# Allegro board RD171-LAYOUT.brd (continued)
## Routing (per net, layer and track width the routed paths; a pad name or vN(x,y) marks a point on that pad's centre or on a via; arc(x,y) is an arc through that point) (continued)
SIG230: length 1.6
  BOTTOM w0.4: 244.25,22.55 R149.1
SIG231: length 3.1
  BOTTOM w0.4: C72.2 233.28,17.3 ; IC14.6 234.55,17.97 234.38,17.97 233.75,18.6 233.3,18.6
SIG234: length 1.8
  BOTTOM w0.3: 234.5,16.5 233.84,16.5 233.24,15.9
  BOTTOM w0.8: IC14.5 234.5,16.5
SIG236: length 1.6
  BOTTOM w0.4: R150.1 244.25,17.8
SIG237: length 1.6
  TOP w0.4: C73.2 233.78,19.57 234.03,19.83 234.55,19.83 IC15.6
SIG242: length 1.8
  TOP w0.3: 233.24,22.1 233.79,21.55 233.95,21.55 234.5,21.3
  TOP w0.8: IC15.5 234.5,21.3
SIG245: length 1.9
  TOP w0.3: 234.5,16.5 234.05,16.7 234.04,16.7 233.24,17.5
  TOP w0.8: IC16.5 234.5,16.5
SIG246: length 2.7
  TOP w0.4: IC16.6 234.28,15.23 234,14.95 233.35,14.95 ; C74.2 233.32,16.1
SIG247: length 1.6
  TOP w0.4: IC15.1 245.8,20.03
SIG249: length 41.5
  TOP w0.3: 172.88,117.3 174.15,117.3 175.15,116.3 v1(176.9,116.3)
  TOP w0.45: 155.18,107.1 155.75,107.1 156.3,107.65 156.3,107.92
  TOP w0.55: 154.55,107.1 IC5.11 155.18,107.1
  TOP w0.6: 154.95,118.75 155.95,117.75 D23.A 156.9,116.6 158.25,115.25 158.25,109 157.1,107.85 156.4,107.85 ; 154.95,118.75 154.4,118.75 ; 154.95,118.75 154.4,119.3 ; 154.4,120.9 153.8,121.5 ; 154.4,120.9 155,121.5 ; 154.4,120.9 Q5.S ; 154.4,120.9 154.4,119.3 ; 154.4,119.3 154.4,118.75 ; 154.4,119.3 153.85,118.75 ; 154.4,118.75 153.85,118.75 ; 153.85,118.75 R28.1
  TOP w1.7: 172.88,117.3 TP15.1
  CONDUCTIVE3 w0.6: v1(176.9,116.3) 174.25,116.3
SIGN254: length 1.5
  TOP w0.7: 152.25,44.7 152.25,44 152.15,43.9 R172.1
SIGN256: length 6.5
  TOP w0.3: v1(145.65,2.3) 144.57,2.3
  TOP w0.7: 144.57,2.3 R177.1
  BOTTOM w0.3: 146.55,3.85 146.55,4.55
  BOTTOM w0.4: 146.55,3.85 C77.2 R96.2 146.35,2 145.95,2 v1(145.65,2.3) 145.3,1.95 144.7,1.95 R97.1
SIGN260: length 7
  BOTTOM w0.3: 146.57,5.22 147.43,5.22 148.45,4.2 149.08,4.2 150.57,2.7 150.57,2.36 ; 151.66,1.7 151.07,1.7 C76.2
  BOTTOM w0.45: 150.57,2.36 C76.2
  BOTTOM w0.58: 151.66,1.7 R170.2 151.86,1.7
SIGN262: length 6.7
  BOTTOM w0.3: 151.66,3.1 151.05,3.1 150.07,4.08 C75.2 149.68,4.9 148.65,4.9 147.68,5.88 146.55,5.88
  BOTTOM w0.58: 151.86,3.1 R169.2 151.66,3.1
SIGN266: length 20.2
  TOP w0.3: 159.35,49.95 160.25,49.95 160.85,49.35 160.85,45.7 156.65,41.5
  TOP w1: 158.95,49.95 158.85,50.05 158.85,51.03 Q2.G
  TOP w1.3: 158.95,49.95 159.35,49.95
SIGN267: length 18.4
  TOP w0.3: 122.5,59.05 122.9,58.65 ; 122.5,59.05 122.5,56.2 ; 122.5,59.05 122.1,58.65 ; 122.5,59.05 122.5,62.4 124,63.9 TP4.1
  TOP w1: 122.75,53.9 122.25,53.4 ; 122.25,53.4 121.75,53.9 ; 122.25,53.4 122.25,55.95 122.5,56.2 ; 122.25,53.4 122.25,52.51 121.5,51.76 FB2.2
SIGN269: length 12.5
  TOP w0.6: IC5.12 153.58,108.37 153.25,108.7 153.25,112.65 152.4,113.5 D42.A 152.4,114.6 ; 152.4,114.6 D43.C ; 152.4,114.6 D23.C
SIGN270: length 1.7
  TOP w0.6: R114.1 149.22,100.55
SIGN271: length 2.3
  BOTTOM w1.5: 168.15,18.3 R179.2 168.15,20.6
SIGN275: length 3
  TOP w0.3: 87.3,78.43 87.3,78.75 86.91,79.14 85.3,79.14
  TOP w0.4: 87.3,78.05 D48.A 87.3,78.43
  TOP w0.7: 85.2,79.14 85.3,79.14
SIGN284: length 1.6
  BOTTOM w0.4: IC13.3 245.8,20.03
SIGN287: length 1.6
  BOTTOM w0.4: IC14.3 245.8,15.23
SIGN289: length 1.6
  TOP w0.4: R197.1 244.25,17.8
SIGN291: length 1.6
  TOP w0.4: R196.1 244.25,22.6
SIGN304: length 2.9
  BOTTOM w0.4: IC21.2 229.68,20.8 229.88,20.6 R186.1 231.6,20.6 R153.1
SIGN305: length 3.1
  BOTTOM w0.4: IC22.2 229.65,16.5 230.05,16.1 230.5,16.1 R188.1 230.5,15.9 R154.1
SIGN314: length 3.8
  TOP w0.4: R155.1 230.85,22 230.5,21.65 R190.1 230.25,21 229.85,20.6 IC23.2
SIGN315: length 3.2
  TOP w0.4: IC24.2 229.6,16.4 230.4,17.2 R192.1 ; R156.1 231.6,17.3 230.55,17.3
SIGN318: length 16.2
  TOP w0.6: D24.C 153.9,69.5 154.9,69.5 157.2,71.8 160.25,71.8 D41.C 163.05,73.05 D40.A ; IC4.12 164.83,71.27 163.65,72.45
SIGN322: length 35.7
  TOP w0.6: IC5.6 150.94,104.56 153.1,102.4 v1(156.2,102.4)
  BOTTOM w0.6: v1(156.2,102.4) 156.2,103.95 165.7,113.45 171.75,113.45 172.65,114.35 D22.C 170.1,115.1 ; 170.1,115.1 D47.C ; 170.1,115.1 D46.A
SIGN325: length 12.1
  TOP w0.6: 171.5,72.7 D44.A 170.85,69.85 170.85,68.8 168.64,66.59 IC4.6 ; D25.C 169.35,72.75 D45.C
SIGN336: length 1.6
  BOTTOM w0.6: 260.1,93 R20.1
SIGN337: length 1.6
  BOTTOM w0.6: D54.A R213.1
SIGN338: length 2.2
  BOTTOM w0.6: R18.1 254.05,109.55
SIGN339: length 3
  BOTTOM w0.6: D52.A 254.85,112.8 ; 254.85,112.8 255.6,112.8 ; 254.85,112.8 255.45,113.4
SIGN341: length 1.7
  BOTTOM w0.6: 262.1,50.3 R24.1 D57.C
SIGN342: length 1.6
  BOTTOM w0.6: D58.A 262,52.45
SIGN343: length 21.3
  TOP w0.6: v1(257.75,76.45) 256.45,76.45 ; 256.75,87.05 Q7.4 v1(256.75,88.05)
  CONDUCTIVE4 w0.6: v1(257.75,76.45) 258,76.7 258,80.05 256.75,81.3 v1(256.75,82.25) v1(256.75,88.05)
  BOTTOM w0.5: R22.2 258.8,71.9 R23.2
  BOTTOM w0.6: v1(256.75,82.25) Q8.4 ; v1(257.75,76.45) 258.8,75.4 R214.2 R23.2
SIGN344: length 2.2
  BOTTOM w0.6: R23.1 254.05,71.55
SIGN345: length 2.8
  BOTTOM w0.6: 254.85,74.8 255.45,75.4 ; 254.85,74.8 D56.A ; 254.85,74.8 255.4,74.8
SIGN355: length 191
  TOP w3.5: T4.1 224.19,41 221.48,43.71 220.28,44.72 218.92,45.51 217.45,46.04 215.9,46.32 215.12,46.35 203.59,46.35 202.98,46.38 201.78,46.59 200.63,47.01 199.57,47.62 198.64,48.4 192.46,54.58 192.1,54.97 191.5,55.83 191.06,56.77 190.79,57.78 190.7,58.83 190.7,64.64 190.64,65.34 190.46,66.01 190.16,66.64 189.76,67.21 189.53,67.47 189.5,67.5 189.5,71.7
  BOTTOM w1: 155.05,92.8 155.8,92.05 ; 155.8,92.05 155.1,91.35 ; 155.8,92.05 170.1,92.05 173.05,95 182.45,95 D19.C
  BOTTOM w3: 148.95,123.8 148.95,117.25 149.47,116.73 149.47,99.58 153.95,95.1 153.95,81.5
  BOTTOM w3.5: 184.95,72.05 189.53,67.47 189.76,67.21 190.16,66.64 190.46,66.01 190.64,65.34 190.7,64.64 190.7,58.83 190.79,57.78 191.06,56.77 191.5,55.83 192.1,54.97 192.46,54.58 198.64,48.4 199.57,47.62 200.63,47.01 201.78,46.59 202.98,46.38 203.59,46.35 215.12,46.35 215.91,46.32 217.45,46.04 218.93,45.51 220.28,44.72 221.49,43.71 224.2,41 T4.1
  vias: v1(188.2,73.6) v1(188.2,72.6) v1(188.2,71.6) v1(188.2,70.6) v1(188.2,69.6) v1(189.2,74.6) v1(189.2,73.6) v1(189.2,72.6) v1(189.2,71.6) v1(189.2,70.6) v1(189.2,69.6) v1(189.2,68.6) v1(190.2,74.6) v1(190.2,73.6) v1(190.2,72.6) v1(190.2,71.6) v1(190.2,70.6) v1(190.2,69.6) v1(190.2,68.6) v1(191.2,73.6) v1(191.2,72.6) v1(191.2,71.6) v1(191.2,70.6) v1(191.2,69.6) v1(191.2,68.6)
SIGN356: length 3.8
  BOTTOM w0.6: T4.5 D14.A R9.2
SIGN360: length 4.8
  BOTTOM w2.8: 262.25,38.2 L5.1 262.25,33.4
SIGN364: length 72.3
  TOP w5: 92.28,50.4 89.98,50.4 88.41,48.83 83.42,48.83 78.54,53.7 76.1,53.7 ; 104.9,32.2 102.75,32.2 C64.2 93.35,43.55
  BOTTOM w5: 104.75,32.2 102.75,32.2 C64.2 93.35,43.55 ; 76.1,53.7 78.54,53.7 83.42,48.83 88.41,48.83 89.98,50.4 92.28,50.4
SIGN366: length 5.3
  TOP w0.5: 129.6,66.13 129.6,68.25 HS1.1
  TOP w0.72: 129.6,65.84 R220.2 129.6,66.13
SIGN369: length 5.3
  TOP w0.5: HS2.1 183,66.52
  TOP w0.7: 183,66.52 R221.2
SIGN371: length 5.3
  TOP w0.5: HS3.1 116.3,47.15 116.3,45.02
  TOP w0.6: 116.3,44.75 R222.2 116.3,45.02
SIGN373: length 5.8
  TOP w0.5: HS4.1 184.6,84.5 184.6,82.02
  TOP w0.6: 184.6,82.02 184.6,81.75
VREF: length 63.1
  TOP w0.6: v1(265.7,23.35) v1(266.95,23.35) 266.95,19.46 266.4,18.91 R207.2 ; R58.2 267.7,13.85 R62.2 v1(268.3,15.35) v1(268.3,16.65) 268.3,16.85 267.7,17.45 266.45,17.45
  CONDUCTIVE3 w0.8: v1(268.3,16.65) v1(268.3,15.35)
  CONDUCTIVE3 w1: 253,13.15 253,13.75 ; 253,13.15 253,12.2 252,11.2 v1(251.4,11.2) ; 253,13.15 252.4,13.75 ; 253,13.75 253,14.35 ; 253,13.75 252.4,13.75 ; 253,14.35 253,18.65 256.05,21.7 262.45,21.7 264.1,23.35 v1(265.7,23.35) ; 253,14.35 252.4,13.75 ; v1(268.3,16.65) 268.3,18.55 266.95,19.9 266.95,22.1 ; 266.95,22.1 v1(266.95,23.35) v1(265.7,23.35) ; 266.95,22.1 v1(265.7,23.35) ; 252.4,13.75 v1(251.4,13.75)
  BOTTOM w0.4: v1(251.4,13.75) R211.2
  BOTTOM w0.45: 262.95,23.15 C99.2
  BOTTOM w0.6: v1(266.95,23.35) v1(265.7,23.35) R44.2 263.15,23.35 262.95,23.15 ; R57.2 267,16.65 v1(268.3,16.65) v1(268.3,15.35) R62.2 268.3,14.4 ; v1(251.4,11.2) 251.65,10.95 252.25,10.95
VREF_PFC: length 40.9
  TOP w0.3: R177.2 145.2,3.7 v1(145.65,3.6)
  CONDUCTIVE3 w0.5: v1(136.3,4.75) v1(137.55,4.75) 144.5,4.75 v1(145.65,3.6) 147,4.95 147,14.75 144.5,17.25 v1(143.65,17.25)
  BOTTOM w0.3: IC3.13 139.6,5.88 139.12,5.4 C42.2 ; 150.05,14.84 147.64,17.25 v1(143.65,17.25)
  BOTTOM w0.4: R97.2 144.95,3.6 v1(145.65,3.6)
  BOTTOM w0.45: C42.2 138.35,5.17 137.93,4.75 v1(137.55,4.75)
  BOTTOM w0.6: v1(136.3,4.75) v1(137.55,4.75)
N03591: length 1.3
  BOTTOM w0.7: R130.1 R116.2
N05004: length 11.7
  TOP w0.6: 144.1,121.5 143.52,120.92 ; 143.52,120.92 Q5.G ; 143.52,120.92 142.94,121.5 ; 143.52,120.92 143.52,119.4 144.17,118.75 R28.2 R133.2 R132.2
N07003: length 4.8
  BOTTOM w2.8: 267.98,83.75 L6.1 267.98,88.55
N07203: length 21.1
  TOP w0.6: v1(257.75,114.45) 256.6,114.45 ; v1(258.07,125.18) 256.9,125.18
  CONDUCTIVE4 w0.6: v1(258.07,125.18) 257.7,125.18 257,124.48 v1(257,120.25) 257,118.8 258,117.8 258,114.7 v1(257.75,114.45)
  BOTTOM w0.5: R18.2 258.8,109.9 R19.2
  BOTTOM w0.6: R18.2 R212.2 258.8,113.4 v1(257.75,114.45) ; v1(257,120.25) 257,121.3
N11927: length 63
  TOP w0.6: v1(288.75,23.95) TP28.1
  TOP w0.8: v1(301.1,58.95) 301.1,57.65 ; v1(307.6,58.95) 307.6,57.65
  CONDUCTIVE4 w0.3: v1(291.2,36.95) 291.7,36.7 293.65,34.75 293.65,28.85 v1(288.75,23.95)
  CONDUCTIVE4 w0.8: v1(291.2,36.95) 289.8,38.35 289.8,55.6 293.15,58.95 v1(301.1,58.95) v1(307.6,58.95)
  BOTTOM w0.8: 291.2,36.05 v1(291.2,36.95) ; Q18.4 307.4,58.76 v1(307.6,58.95) ; Q17.4 300.9,58.76 v1(301.1,58.95)
N043041: length 1.9
  TOP w0.6: 161.65,75.3 D40.C
N043160: length 2.6
  TOP w0.6: D41.A R127.1
N043261: length 1.6
  TOP w0.6: D44.C R134.1
N043380: length 1.6
  TOP w0.6: D45.A R135.1
N043600: length 1.6
  TOP w0.6: R133.1 149.6,116.9
N043701: length 1.6
  BOTTOM w0.6: R136.1 D46.C
N043820: length 1.6
  BOTTOM w0.6: R137.1 D47.A
N66342: length 37.6
  TOP w0.5: 181.31,21.81 184.38,21.81 186.92,24.35 Q80.D
  TOP w1: T8.3 209.97,24.5
  TOP w1.68: 180.1,21.81 181.31,21.81
  TOP w1.9: 189.55,23.45 Q80.D
  TOP w2: 189.55,23.45 190.94,23.45 195.69,18.7 207.15,18.7 209.97,21.52 209.97,24.5
N66362: length 4.5
  BOTTOM w0.6: 188.6,33.45 191.95,33.45 ; 188.6,33.45 188.6,34.55 ; 188.6,33.45 R803.1
N14550647: length 5.4
  BOTTOM w0.4: 184.47,46.75 R809.2 R808.1 ; 184.47,46.75 184.6,46.75 ; 184.47,46.75 C812.2 ; 184.47,45.6 IC80.VS
N14553110: length 30.8
  BOTTOM w2: 242.45,5.45 239,2 213.1,2
N14557584: length 84.3
  CONDUCTIVE4 w0.3: C800.2 191.15,17.6 189.11,19.64 185.41,19.64 178.85,26.2 v1(178.85,30.4)
  BOTTOM w0.3: v1(178.85,30.4) 181.05,32.6 181.05,35.7 182.5,37.15 183,37.15
  BOTTOM w0.59: 183,37.15 183.2,37.15
  BOTTOM w1: F8.2 180.45,15
  BOTTOM w2: 217.4,24.5 217.4,22.1 211.95,16.65 191.4,16.65 ; 191.4,16.65 191.4,16.65 ; 191.4,16.65 191.4,16.66 ; T8.1 217.39,30.59 R800.2 ; 180.45,15.25 180.45,15.37 180.46,15.55 180.52,15.89 180.64,16.22 180.81,16.52 181.04,16.79 183.56,19.31 183.69,19.43 183.98,19.63 184.29,19.78 184.63,19.87 184.98,19.9 187.32,19.9 187.5,19.89 187.84,19.83 188.17,19.71 188.47,19.54 188.74,19.31 191.4,16.66 ; 191.4,16.65 191.4,16.66 ; 191.4,16.65 191.4,15.59
N14557651: length 1.4
  BOTTOM w0.6: D81.C 178.55,45.15 178.2,44.8
N14557692: length 3.5
  BOTTOM w0.6: 183.2,42.6 IC80.VDD C802.2 R806.2
N14557973: length 1.9
  BOTTOM w0.4: 185.74,44.45 185.74,42.6
N14565222: length 2.2
  BOTTOM w0.6: 185.74,37.2 185.74,36.06 R802.1
N14565783: length 2.7
  BOTTOM w0.6: IC80.CS C803.2 ; R804.1 188.6,37.15
N14565980: length 6.2
  TOP w1.5: T8.5 200.92,29.97 v1(201.45,30.5)
  vias: v1(201.45,31.4) v1(202.35,31.4) v1(202.35,30.5)
N16776505: length 4.8
  BOTTOM w0.6: 186.11,29.35 186.5,30.5 186.5,31.95 ; R803.2 186.5,32
N16975142: length 20.3
  TOP w6.1: T6.4 T6.3
  BOTTOM w6.1: T6.4 T6.3
N16985418: length 20.3
  TOP w6.1: T5.4 T5.3
  BOTTOM w6.1: T5.4 T5.3

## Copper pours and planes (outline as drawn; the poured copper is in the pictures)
P48V on TOP: 294.5,55.73 294.5,55.75 294.51,55.76 294.96,56.21 294.98,56.22 295,56.23 315.45,56.23 315.47,56.22 315.49,56.21 315.74,55.96 315.75,55.95 315.75,55.93 315.75,36.21 315.75,36.19 315.74,36.17 312.83,33.26 312.81,33.25 312.79,33.25 297.47,33.25 297.45,33.25 297.44,33.26 294.51,36.19 294.5,36.2 294.5,36.22 ; 4 cut-outs
P48V on BOTTOM: 294.5,55.73 294.5,55.75 294.51,55.76 294.96,56.21 294.98,56.22 295,56.23 313.45,56.23 313.47,56.22 313.49,56.21 313.86,55.84 313.89,55.8 313.9,55.74 313.9,32.95 313.89,32.92 313.66,31.96 314.14,31.11 314.15,31.1 315.09,30.16 315.1,30.15 315.1,30.13 315.1,28.95 315.09,28.91 315.05,28.9 314.04,28.9 314.01,28.91 313.46,29.46 313.25,29.6 313,29.65 308.09,29.65 307.9,29.61 307.73,29.5 306.86,28.63 306.83,28.61 306.79,28.6 304.9,28.6 304.87,28.61 304.78,28.72 304.75,28.85 304.75,29.83 304.73,29.94 304.66,30.04 303.19,31.51 303.08,31.62 302.94,31.72 302.76,31.75 295.02,31.75 295,31.75 294.99,31.76 294.51,32.24 294.5,32.25 294.5,32.27 ; 4 cut-outs
P48V on CONDUCTIVE2, CONDUCTIVE5: 301.42,46.1 301.4,46.1 301.39,46.11 300.66,46.84 300.65,46.85 300.65,46.87 300.65,50.73 300.65,50.75 300.66,50.76 300.79,50.89 300.8,50.9 300.82,50.9 309.48,50.9 309.5,50.9 309.51,50.89 310.24,50.16 310.25,50.15 310.25,50.13 310.25,46.27 310.25,46.25 310.24,46.24 310.11,46.11 310.1,46.1 310.08,46.1
P48V on CONDUCTIVE3: 294.5,55.73 294.5,55.75 294.51,55.76 294.96,56.21 294.98,56.22 295,56.23 315.5,56.23 315.52,56.22 315.54,56.21 315.78,55.97 315.8,55.95 315.8,55.93 315.8,36.19 315.8,36.17 315.79,36.15 312.9,33.26 312.88,33.25 312.86,33.25 297.47,33.25 297.45,33.25 297.44,33.26 294.51,36.19 294.5,36.2 294.5,36.22 ; 1 cut-out
VCC12R0_1 on TOP: 176.52,40.15 176.5,40.15 176.49,40.16 176.01,40.64 176,40.65 176,40.67 176,41.83 176,41.85 176.01,41.86 176.24,42.09 176.25,42.1 176.27,42.1 177.33,42.1 177.35,42.1 177.36,42.09 177.59,41.86 177.6,41.85 177.6,41.83 177.6,40.75 177.6,40.73 177.59,40.71 177.04,40.16 177.02,40.15 177,40.15
VCC12R0_2 on BOTTOM: 247.05,1.6 247.01,1.61 247,1.65 247,3.27 246.97,3.37 246.94,3.41 246.61,3.74 246.6,3.75 246.6,3.77 246.6,9.58 246.6,9.6 246.61,9.61 248.14,11.14 248.19,11.23 248.2,11.28 248.2,12.9 248.21,12.94 248.25,12.95 249.55,12.95 249.59,12.94 249.6,12.9 249.6,9.98 249.63,9.88 249.66,9.84 250.2,9.3 250.29,9.25 250.34,9.24 267.95,9.24 267.97,9.24 267.99,9.23 268.58,8.64 268.59,8.62 268.6,8.6 268.6,7.95 268.59,7.93 268.58,7.92 268.13,7.46 268.13,6.05 268.12,6.01 268.08,6 249.08,6 248.98,5.97 248.94,5.94 248.06,5.06 248.01,4.97 248,4.92 248,1.65 247.99,1.61 247.95,1.6
AUX on BOTTOM: 196.45,24.45 196.41,24.46 196.4,24.5 196.4,26.25 196.65,26.5 197.95,26.5 197.99,26.49 198,26.45 198,25.27 198,25.25 197.99,25.24 197.96,25.21 197.91,25.12 197.9,25.07 197.9,24.5 197.89,24.46 197.85,24.45
CONN002 on TOP: 146.91,78.8 146.91,84.2 150.09,84.2 150.09,78.8
CONN002 on BOTTOM: 169.91,78.9 169.81,78.94 169.76,79.05 169.76,84.05 169.81,84.16 169.91,84.2 172.79,84.2 172.89,84.16 172.94,84.05 172.94,79.05 172.89,78.94 172.79,78.9
CONN002 on BOTTOM: 148.99,78.8 148.96,78.81 148.93,78.82 146.93,80.82 146.92,80.84 146.91,80.87 146.91,84.12 146.93,84.18 146.99,84.2 150.01,84.2 150.07,84.18 150.09,84.12 150.09,78.88 150.07,78.82 150.01,78.8
CONN002 on CONDUCTIVE3: outline of 127 points within 146.65,79 205.5,125.79
CONN002 on CONDUCTIVE4: outline of 133 points within 146.65,79 205.5,125.79 ; 1 cut-out
CONN003 on TOP: 201.65,51.49 201.63,51.49 201.62,51.5 195.5,57.63 195.13,58.18 195,58.83 195,64.64 194.8,66.44 194.22,68.15 194.15,68.31 194.15,68.33 194.15,73.68 193.95,74.69 193.37,75.55 192.15,76.77 192.09,76.83 191.26,77.36 190.28,77.55 189.42,77.55 189.4,77.55 189.39,77.56 189.16,77.79 189.15,77.8 189.15,77.82 189.15,81.58 189.15,81.6 189.16,81.61 189.39,81.84 189.4,81.85 189.42,81.85 195.88,81.85 195.91,81.84 198.09,79.66 198.1,79.65 198.1,79.63 198.1,63.79 198.53,61.65 199.74,59.83 202.86,56.71 203.71,56.71 203.73,56.71 203.74,56.7 206.05,54.39 206.05,54.37 206.05,52.62 206.05,52.6 206.04,52.59 204.95,51.5 204.94,51.49 204.92,51.49
CONN003 on BOTTOM: outline of 111 points within 174.2,51.49 206.05,117.05
CONN004 on TOP: outline of 140 points within 274.4,48 313.45,123.05
CONN004 on BOTTOM: outline of 134 points within 275.9,48 309.5,123.05
CONN004 on CONDUCTIVE2, CONDUCTIVE5: 296.12,59.9 296.1,59.9 296.09,59.91 295.36,60.64 295.35,60.65 295.35,60.67 295.35,66.93 295.35,66.95 295.36,66.96 295.49,67.09 295.5,67.1 295.52,67.1 301.78,67.1 301.8,67.1 301.81,67.09 302.54,66.36 302.55,66.35 302.55,66.33 302.55,60.07 302.55,60.05 302.54,60.04 302.41,59.91 302.4,59.9 302.38,59.9
CONN004 on CONDUCTIVE3: 281.45,102.33 281.43,102.44 281.36,102.54 274.41,109.49 274.4,109.5 274.4,109.52 274.4,122.78 274.41,122.81 274.69,123.09 274.7,123.1 274.72,123.1 282.08,123.1 282.1,123.1 282.11,123.09 287.71,117.49 288.03,117.28 288.41,117.2 296.03,117.2 296.05,117.2 296.06,117.19 296.96,116.29 297.27,116.08 297.66,116 306.21,116 306.28,115.97 309.47,112.78 309.5,112.71 309.5,66.66 309.57,66.41 309.65,66.3 313.44,62.51 313.45,62.5 313.45,62.48 313.45,57.12 313.39,56.98 313.25,56.92 295,56.92 294.98,56.93 294.96,56.94 294.52,57.38 294.5,57.4 294.5,57.42 294.5,83.35 294.47,83.42 294.4,83.45 293.9,83.45 293.83,83.42 293.8,83.35 293.8,48.97 293.8,48.95 293.79,48.94 292.86,48.01 292.85,48 292.83,48 283.32,48 283.3,48 283.29,48.01 281.46,49.84 281.45,49.85 281.45,49.87 ; 2 cut-outs
FG2 on TOP: 4.5,7.35 4.54,7.46 4.65,7.5 9.58,7.5 9.65,7.49 9.79,7.41 12.91,4.29 12.96,4.23 13,4.08 13,3.56 12.99,3.5 12.96,3.46 10.09,0.59 10.03,0.54 9.88,0.5 6,0.5 5.41,0.62 4.94,0.94 4.61,1.44 4.5,2 ; 1 cut-out
FG3 on TOP: 61.35,42.52 61.33,42.53 61.31,42.54 60.54,43.31 60.53,43.33 60.52,43.35 60.52,49.93 60.57,50.03 60.67,50.08 61.83,50.08 61.93,50.03 61.98,49.92 61.98,49.47 61.98,49.43 62,49.4 65.11,46.29 65.14,46.25 65.15,46.19 65.17,46.17 65.17,46.15 65.17,45.73 67.13,43.77 67.17,43.66 67.17,42.67 67.13,42.57 67.03,42.52
FG3 on BOTTOM: 60.67,44.35 60.57,44.39 60.52,44.5 60.52,49.92 60.57,50.03 60.67,50.08 61.83,50.08 61.93,50.03 61.98,49.92 61.98,49.47 61.98,49.43 62,49.4 64.71,46.69 64.74,46.65 64.75,46.59 64.75,44.5 64.71,44.39 64.6,44.35
FG3 on BOTTOM: 63.9,42.52 63.79,42.57 63.75,42.67 63.75,43.85 63.79,43.96 63.9,44 64.9,44 64.9,44.55 64.94,44.66 65.05,44.7 66.14,44.7 66.2,44.69 66.24,44.66 67.01,43.89 67.05,43.79 67.05,42.67 67.01,42.57 66.9,42.52
FG5 on BOTTOM: 176.54,1.61 176.47,1.71 176.45,1.82 176.45,2.58 176.47,2.69 176.54,2.79 177.66,3.91 177.76,3.98 177.87,4 178.6,4 178.71,3.96 178.75,3.86 181.25,1.5 183.75,3.86 183.75,3.88 183.75,5.78 183.78,5.83 183.84,5.81 187.55,2.1 188.35,2.1 188.39,2.09 188.4,2.05 188.4,1.35 188.39,1.31 188.35,1.3 187.55,1.3 186.76,0.51 186.75,0.5 186.73,0.5 177.77,0.5 177.66,0.52 177.56,0.59
FG6 on BOTTOM: 307.58,4.8 307.6,4.8 307.61,4.79 308.11,4.29 308.21,4.22 308.32,4.2 311.1,4.2 311.4,4.5 311.4,10.56 316.37,15.54 316.53,15.81 316.55,15.96 316.55,28.03 316.52,28.2 316.42,28.35 316.31,28.45 316.3,28.49 316.3,30.15 316.31,30.19 316.35,30.2 317.38,30.2 317.4,30.19 317.51,30.14 317.99,29.66 318,29.63 318,2 317.56,0.94 316.5,0.5 307.87,0.5 307.76,0.52 307.66,0.59 307.09,1.16 307.02,1.26 307,1.37 307,4.75 307.01,4.79 307.05,4.8 ; 2 cut-outs
FG7 on BOTTOM: 308.2,121.5 308.24,121.61 308.35,121.65 309.15,121.65 309.38,121.88 309.42,121.91 309.48,121.92 310.52,121.92 310.63,121.94 310.73,122.01 310.87,122.15 310.95,122.29 310.96,122.36 310.96,124.72 311,124.83 312.59,126.41 312.65,126.46 312.8,126.5 316.5,126.5 317.09,126.38 317.56,126.06 317.89,125.56 318,125 318,123.05 318,123.04 315.6,119.68 311.66,120.95 308.35,120.95 308.24,120.99 308.2,121.1 ; 1 cut-out
HS1_1 on TOP (solid shape): 181.37,125.3 181.31,125.72 181.73,125.77 185.03,123.24 185.15,123 185.03,122.76 181.73,120.23 181.42,120.19 181.25,120.46 181.28,120.6 181.37,120.7 182.08,121.25 182.08,124.75
HS1_2 on TOP (solid shape): 88.33,125.75 88.6,125.78 88.74,125.55 88.71,125.44 88.64,125.36 87.93,124.79 87.93,121.21 88.64,120.64 88.68,120.29 88.33,120.25 85.1,122.8 85,123 85.1,123.2
IN on TOP (solid shape): 196.3,36.86 196.35,36.85 197.27,36.63 197.55,36.45 197.66,36.14 197.6,35.9 197.43,35.72 197.13,35.26 196.59,35.35 195.78,36.16 195.74,36.36 195.88,36.72 196.24,36.86
LGND on TOP: outline of 236 points within 254.53,6.85 318,126.5 ; 5 cut-outs
LGND on TOP: outline of 85 points within 254.53,63.5 265.06,88.25
LGND on BOTTOM: 260.4,69.6 260.1,69.9 260.1,76.7 259.9,76.9 259.47,76.9 259.45,76.9 259.44,76.91 259.26,77.09 259.25,77.1 259.25,77.12 259.25,78.53 259.25,78.55 259.26,78.56 259.54,78.84 259.55,78.85 259.57,78.85 262.05,78.85 262.09,78.84 262.1,78.8 262.1,69.6
LGND on BOTTOM: outline of 103 points within 256.02,33.5 317,126.5 ; 7 cut-outs
LGND on BOTTOM: 303.55,28.6 303.68,28.28 304,28.15 306.79,28.15 307,28.19 307.18,28.31 308.05,29.19 308.07,29.2 308.09,29.2 313,29.2 313.08,29.18 313.14,29.14 313.7,28.58 313.9,28.47 314.02,28.45 315.63,28.45 315.65,28.45 315.66,28.44 316.09,28.01 316.1,28 316.1,27.98 316.1,15.96 316.06,15.86 310.99,10.79 310.92,10.69 310.9,10.58 310.9,5.94 310.89,5.88 310.86,5.83 310.78,5.75 310.65,5.56 310.6,5.33 310.6,5 310.56,4.89 310.45,4.85 308.27,4.85 308.25,4.85 308.24,4.86 307.89,5.21 307.79,5.28 307.68,5.3 298.72,5.3 298.61,5.32 298.51,5.39 297.34,6.56 297.02,6.77 296.64,6.85 295.07,6.85 294.96,6.87 294.86,6.94 294.54,7.26 294.51,7.3 294.5,7.36 294.5,30.78 294.5,30.8 294.51,30.81 294.99,31.29 295,31.3 295.02,31.3 302.73,31.3 302.75,31.3 302.76,31.29 303.54,30.51 303.55,30.5 303.55,30.48 ; 3 cut-outs
LGND on BOTTOM: 243.12,1.6 243.1,1.6 243.09,1.61 242.91,1.79 242.9,1.8 242.9,1.82 242.9,2.98 242.9,3 242.91,3.01 243.09,3.19 243.1,3.2 243.12,3.2 244.75,3.2 244.79,3.19 244.8,3.15 244.8,1.65 244.79,1.61 244.75,1.6
LGND on BOTTOM: 256.67,63.5 256.65,63.5 256.64,63.51 256.29,63.86 256.28,63.88 256.27,63.9 256.27,65.24 256.19,65.45 255.97,65.54 254.68,65.54 254.57,65.58 254.53,65.69 254.53,68.88 254.54,68.92 254.57,68.93 255.85,68.93 255.95,68.96 255.99,68.99 256.24,69.24 256.29,69.33 256.3,69.38 256.3,70.08 256.3,70.1 256.31,70.11 256.59,70.39 256.6,70.4 256.62,70.4 259.38,70.4 259.4,70.4 259.41,70.39 259.64,70.16 259.65,70.15 259.65,70.13 259.65,69.73 259.68,69.63 259.71,69.59 260.14,69.16 260.23,69.11 260.28,69.1 262.23,69.1 262.25,69.1 262.26,69.09 263.09,68.26 263.1,68.25 263.1,68.23 263.1,64.32 263.1,64.3 263.09,64.29 262.31,63.51 262.3,63.5 262.28,63.5
LGND on BOTTOM: 260.4,107.6 260.1,107.9 260.1,114.7 259.9,114.9 259.47,114.9 259.45,114.9 259.44,114.91 259.26,115.09 259.25,115.1 259.25,115.12 259.25,116.53 259.25,116.55 259.26,116.56 259.54,116.84 259.55,116.85 259.57,116.85 262.05,116.85 262.09,116.84 262.1,116.8 262.1,107.6
LGND on BOTTOM: 256.67,101.5 256.65,101.5 256.64,101.51 256.29,101.86 256.28,101.88 256.27,101.9 256.27,103.24 256.19,103.45 255.97,103.54 254.68,103.54 254.57,103.58 254.53,103.69 254.53,106.88 254.54,106.92 254.57,106.93 255.85,106.93 255.95,106.96 255.99,106.99 256.24,107.24 256.29,107.33 256.3,107.38 256.3,108.08 256.3,108.1 256.31,108.11 256.59,108.39 256.6,108.4 256.62,108.4 259.43,108.4 259.45,108.4 259.46,108.39 259.7,108.15 259.7,108.13 259.7,107.68 259.73,107.58 259.76,107.54 260.14,107.16 260.23,107.11 260.28,107.1 262.23,107.1 262.25,107.1 262.26,107.09 263.09,106.26 263.1,106.25 263.1,106.23 263.1,102.32 263.1,102.3 263.09,102.29 262.31,101.51 262.3,101.5 262.28,101.5
LGND on CONDUCTIVE2: outline of 136 points within 190.9,0.5 318,126.5 ; 110 cut-outs
LGND on CONDUCTIVE5: outline of 129 points within 190.9,0.5 318,126.5 ; 110 cut-outs
Net_1 on BOTTOM: 15.75,-3.5 16.81,-3.06 17.25,-2 101.25,-2 101.69,-3.06 102.75,-3.5 103.25,-3.5 103.82,-3.39 104.31,-3.06 106.09,-1.29 106.41,-1.29 108.19,-3.06 108.19,-3.06 108.68,-3.39 109.25,-3.5 109.75,-3.5 110.81,-3.06 111.25,-2 195.25,-2 195.69,-3.06 196.75,-3.5 197.25,-3.5 197.82,-3.39 198.31,-3.06 200.09,-1.29 200.41,-1.29 202.19,-3.06 202.19,-3.06 202.68,-3.39 203.25,-3.5 203.75,-3.5 204.81,-3.06 205.25,-2 301.25,-2 301.69,-3.06 302.75,-3.5 303.25,-3.5 303.82,-3.39 304.31,-3.06 306.09,-1.29 306.41,-1.29 308.19,-3.06 308.19,-3.06 308.68,-3.39 309.25,-3.5 309.75,-3.5 310.81,-3.06 311.25,-2 317.5,-2 317.5,-7 1,-7 1,-2 7.25,-2 7.69,-3.06 8.75,-3.5 9.25,-3.5 9.82,-3.39 10.31,-3.06 12.09,-1.29 12.41,-1.29 14.19,-3.06 14.19,-3.06 14.68,-3.39 15.25,-3.5 ; 4 cut-outs
Net_2 on BOTTOM: 302.75,130.5 301.69,130.06 301.25,129 205.25,129 204.81,130.06 203.75,130.5 203.25,130.5 202.68,130.39 202.19,130.06 200.41,128.29 200.09,128.29 198.31,130.06 197.82,130.39 197.25,130.5 196.75,130.5 195.69,130.06 195.25,129 81.25,129 80.81,130.06 79.75,130.5 79.25,130.5 78.68,130.39 78.19,130.06 76.41,128.29 76.09,128.29 74.31,130.06 73.82,130.39 73.25,130.5 72.75,130.5 71.69,130.06 71.25,129 66,129 65.31,128.94 64.63,128.76 64,128.46 63.43,128.06 62.94,127.57 62.54,127 62.24,126.37 62.06,125.69 62,125 62,77 17.25,77 16.81,78.06 15.75,78.5 15.25,78.5 14.68,78.39 14.19,78.06 12.41,76.29 12.09,76.29 10.31,78.06 10.31,78.06 9.82,78.39 9.25,78.5 8.75,78.5 7.69,78.06 7.25,77 1,77 1,134 317.5,134 317.5,129 311.25,129 310.81,130.06 309.75,130.5 309.25,130.5 308.68,130.39 308.19,130.06 306.41,128.29 306.09,128.29 304.31,130.06 303.82,130.39 303.25,130.5 ; 4 cut-outs
Net_3 on CONDUCTIVE5: 15.75,-3.5 16.81,-3.06 17.25,-2 101.25,-2 101.69,-3.06 102.75,-3.5 103.25,-3.5 103.82,-3.39 104.31,-3.06 106.09,-1.29 106.41,-1.29 108.19,-3.06 108.19,-3.06 108.68,-3.39 109.25,-3.5 109.75,-3.5 110.81,-3.06 111.25,-2 195.25,-2 195.69,-3.06 196.75,-3.5 197.25,-3.5 197.82,-3.39 198.31,-3.06 200.09,-1.29 200.41,-1.29 202.19,-3.06 202.19,-3.06 202.68,-3.39 203.25,-3.5 203.75,-3.5 204.81,-3.06 205.25,-2 301.25,-2 301.69,-3.06 302.75,-3.5 303.25,-3.5 303.82,-3.39 304.31,-3.06 306.09,-1.29 306.41,-1.29 308.19,-3.06 308.19,-3.06 308.68,-3.39 309.25,-3.5 309.75,-3.5 310.81,-3.06 311.25,-2 317.5,-2 317.5,-7 1,-7 1,-2 7.25,-2 7.69,-3.06 8.75,-3.5 9.25,-3.5 9.82,-3.39 10.31,-3.06 12.09,-1.29 12.41,-1.29 14.19,-3.06 14.19,-3.06 14.68,-3.39 15.25,-3.5 ; 2 cut-outs
Net_4 on CONDUCTIVE5: 302.75,130.5 301.69,130.06 301.25,129 205.25,129 204.81,130.06 203.75,130.5 203.25,130.5 202.68,130.39 202.19,130.06 200.41,128.29 200.09,128.29 198.31,130.06 197.82,130.39 197.25,130.5 196.75,130.5 195.69,130.06 195.25,129 81.25,129 80.81,130.06 79.75,130.5 79.25,130.5 78.68,130.39 78.19,130.06 76.41,128.29 76.09,128.29 74.31,130.06 73.82,130.39 73.25,130.5 72.75,130.5 71.69,130.06 71.25,129 66,129 65.31,128.94 64.63,128.76 64,128.46 63.43,128.06 62.94,127.57 62.54,127 62.24,126.37 62.06,125.69 62,125 62,77 17.25,77 16.81,78.06 15.75,78.5 15.25,78.5 14.68,78.39 14.19,78.06 12.41,76.29 12.09,76.29 10.31,78.06 10.31,78.06 9.82,78.39 9.25,78.5 8.75,78.5 7.69,78.06 7.25,77 1,77 1,134 317.5,134 317.5,129 311.25,129 310.81,130.06 309.75,130.5 309.25,130.5 308.68,130.39 308.19,130.06 306.41,128.29 306.09,128.29 304.31,130.06 303.82,130.39 303.25,130.5 ; 2 cut-outs
Net_5 on CONDUCTIVE4: 15.75,-3.5 16.81,-3.06 17.25,-2 101.25,-2 101.69,-3.06 102.75,-3.5 103.25,-3.5 103.82,-3.39 104.31,-3.06 106.09,-1.29 106.41,-1.29 108.19,-3.06 108.19,-3.06 108.68,-3.39 109.25,-3.5 109.75,-3.5 110.81,-3.06 111.25,-2 195.25,-2 195.69,-3.06 196.75,-3.5 197.25,-3.5 197.82,-3.39 198.31,-3.06 200.09,-1.29 200.41,-1.29 202.19,-3.06 202.19,-3.06 202.68,-3.39 203.25,-3.5 203.75,-3.5 204.81,-3.06 205.25,-2 301.25,-2 301.69,-3.06 302.75,-3.5 303.25,-3.5 303.82,-3.39 304.31,-3.06 306.09,-1.29 306.41,-1.29 308.19,-3.06 308.19,-3.06 308.68,-3.39 309.25,-3.5 309.75,-3.5 310.81,-3.06 311.25,-2 317.5,-2 317.5,-7 1,-7 1,-2 7.25,-2 7.69,-3.06 8.75,-3.5 9.25,-3.5 9.82,-3.39 10.31,-3.06 12.09,-1.29 12.41,-1.29 14.19,-3.06 14.19,-3.06 14.68,-3.39 15.25,-3.5 ; 2 cut-outs
Net_6 on CONDUCTIVE4: 302.75,130.5 301.69,130.06 301.25,129 205.25,129 204.81,130.06 203.75,130.5 203.25,130.5 202.68,130.39 202.19,130.06 200.41,128.29 200.09,128.29 198.31,130.06 197.82,130.39 197.25,130.5 196.75,130.5 195.69,130.06 195.25,129 81.25,129 80.81,130.06 79.75,130.5 79.25,130.5 78.68,130.39 78.19,130.06 76.41,128.29 76.09,128.29 74.31,130.06 73.82,130.39 73.25,130.5 72.75,130.5 71.69,130.06 71.25,129 66,129 65.31,128.94 64.63,128.76 64,128.46 63.43,128.06 62.94,127.57 62.54,127 62.24,126.37 62.06,125.69 62,125 62,77 17.25,77 16.81,78.06 15.75,78.5 15.25,78.5 14.68,78.39 14.19,78.06 12.41,76.29 12.09,76.29 10.31,78.06 10.31,78.06 9.82,78.39 9.25,78.5 8.75,78.5 7.69,78.06 7.25,77 1,77 1,134 317.5,134 317.5,129 311.25,129 310.81,130.06 309.75,130.5 309.25,130.5 308.68,130.39 308.19,130.06 306.41,128.29 306.09,128.29 304.31,130.06 303.82,130.39 303.25,130.5 ; 2 cut-outs
Net_7 on CONDUCTIVE3: 15.75,-3.5 16.81,-3.06 17.25,-2 101.25,-2 101.69,-3.06 102.75,-3.5 103.25,-3.5 103.82,-3.39 104.31,-3.06 106.09,-1.29 106.41,-1.29 108.19,-3.06 108.19,-3.06 108.68,-3.39 109.25,-3.5 109.75,-3.5 110.81,-3.06 111.25,-2 195.25,-2 195.69,-3.06 196.75,-3.5 197.25,-3.5 197.82,-3.39 198.31,-3.06 200.09,-1.29 200.41,-1.29 202.19,-3.06 202.19,-3.06 202.68,-3.39 203.25,-3.5 203.75,-3.5 204.81,-3.06 205.25,-2 301.25,-2 301.69,-3.06 302.75,-3.5 303.25,-3.5 303.82,-3.39 304.31,-3.06 306.09,-1.29 306.41,-1.29 308.19,-3.06 308.19,-3.06 308.68,-3.39 309.25,-3.5 309.75,-3.5 310.81,-3.06 311.25,-2 317.5,-2 317.5,-7 1,-7 1,-2 7.25,-2 7.69,-3.06 8.75,-3.5 9.25,-3.5 9.82,-3.39 10.31,-3.06 12.09,-1.29 12.41,-1.29 14.19,-3.06 14.19,-3.06 14.68,-3.39 15.25,-3.5 ; 2 cut-outs
Net_8 on CONDUCTIVE3: 302.75,130.5 301.69,130.06 301.25,129 205.25,129 204.81,130.06 203.75,130.5 203.25,130.5 202.68,130.39 202.19,130.06 200.41,128.29 200.09,128.29 198.31,130.06 197.82,130.39 197.25,130.5 196.75,130.5 195.69,130.06 195.25,129 81.25,129 80.81,130.06 79.75,130.5 79.25,130.5 78.68,130.39 78.19,130.06 76.41,128.29 76.09,128.29 74.31,130.06 73.82,130.39 73.25,130.5 72.75,130.5 71.69,130.06 71.25,129 66,129 65.31,128.94 64.63,128.76 64,128.46 63.43,128.06 62.94,127.57 62.54,127 62.24,126.37 62.06,125.69 62,125 62,77 17.25,77 16.81,78.06 15.75,78.5 15.25,78.5 14.68,78.39 14.19,78.06 12.41,76.29 12.09,76.29 10.31,78.06 10.31,78.06 9.82,78.39 9.25,78.5 8.75,78.5 7.69,78.06 7.25,77 1,77 1,134 317.5,134 317.5,129 311.25,129 310.81,130.06 309.75,130.5 309.25,130.5 308.68,130.39 308.19,130.06 306.41,128.29 306.09,128.29 304.31,130.06 303.82,130.39 303.25,130.5 ; 2 cut-outs
Net_9 on CONDUCTIVE2: 15.75,-3.5 16.81,-3.06 17.25,-2 101.25,-2 101.69,-3.06 102.75,-3.5 103.25,-3.5 103.82,-3.39 104.31,-3.06 106.09,-1.29 106.41,-1.29 108.19,-3.06 108.19,-3.06 108.68,-3.39 109.25,-3.5 109.75,-3.5 110.81,-3.06 111.25,-2 195.25,-2 195.69,-3.06 196.75,-3.5 197.25,-3.5 197.82,-3.39 198.31,-3.06 200.09,-1.29 200.41,-1.29 202.19,-3.06 202.19,-3.06 202.68,-3.39 203.25,-3.5 203.75,-3.5 204.81,-3.06 205.25,-2 301.25,-2 301.69,-3.06 302.75,-3.5 303.25,-3.5 303.82,-3.39 304.31,-3.06 306.09,-1.29 306.41,-1.29 308.19,-3.06 308.19,-3.06 308.68,-3.39 309.25,-3.5 309.75,-3.5 310.81,-3.06 311.25,-2 317.5,-2 317.5,-7 1,-7 1,-2 7.25,-2 7.69,-3.06 8.75,-3.5 9.25,-3.5 9.82,-3.39 10.31,-3.06 12.09,-1.29 12.41,-1.29 14.19,-3.06 14.19,-3.06 14.68,-3.39 15.25,-3.5 ; 2 cut-outs
Net_10 on CONDUCTIVE2: 302.75,130.5 301.69,130.06 301.25,129 205.25,129 204.81,130.06 203.75,130.5 203.25,130.5 202.68,130.39 202.19,130.06 200.41,128.29 200.09,128.29 198.31,130.06 197.82,130.39 197.25,130.5 196.75,130.5 195.69,130.06 195.25,129 81.25,129 80.81,130.06 79.75,130.5 79.25,130.5 78.68,130.39 78.19,130.06 76.41,128.29 76.09,128.29 74.31,130.06 73.82,130.39 73.25,130.5 72.75,130.5 71.69,130.06 71.25,129 66,129 65.31,128.94 64.63,128.76 64,128.46 63.43,128.06 62.94,127.57 62.54,127 62.24,126.37 62.06,125.69 62,125 62,77 17.25,77 16.81,78.06 15.75,78.5 15.25,78.5 14.68,78.39 14.19,78.06 12.41,76.29 12.09,76.29 10.31,78.06 10.31,78.06 9.82,78.39 9.25,78.5 8.75,78.5 7.69,78.06 7.25,77 1,77 1,134 317.5,134 317.5,129 311.25,129 310.81,130.06 309.75,130.5 309.25,130.5 308.68,130.39 308.19,130.06 306.41,128.29 306.09,128.29 304.31,130.06 303.82,130.39 303.25,130.5 ; 2 cut-outs
Net_11 on TOP: 15.75,-3.5 16.81,-3.06 17.25,-2 101.25,-2 101.69,-3.06 102.75,-3.5 103.25,-3.5 103.82,-3.39 104.31,-3.06 106.09,-1.29 106.41,-1.29 108.19,-3.06 108.19,-3.06 108.68,-3.39 109.25,-3.5 109.75,-3.5 110.81,-3.06 111.25,-2 195.25,-2 195.69,-3.06 196.75,-3.5 197.25,-3.5 197.82,-3.39 198.31,-3.06 200.09,-1.29 200.41,-1.29 202.19,-3.06 202.19,-3.06 202.68,-3.39 203.25,-3.5 203.75,-3.5 204.81,-3.06 205.25,-2 301.25,-2 301.69,-3.06 302.75,-3.5 303.25,-3.5 303.82,-3.39 304.31,-3.06 306.09,-1.29 306.41,-1.29 308.19,-3.06 308.19,-3.06 308.68,-3.39 309.25,-3.5 309.75,-3.5 310.81,-3.06 311.25,-2 317.5,-2 317.5,-7 1,-7 1,-2 7.25,-2 7.69,-3.06 8.75,-3.5 9.25,-3.5 9.82,-3.39 10.31,-3.06 12.09,-1.29 12.41,-1.29 14.19,-3.06 14.19,-3.06 14.68,-3.39 15.25,-3.5 ; 4 cut-outs
Net_12 on TOP: 302.75,130.5 301.69,130.06 301.25,129 205.25,129 204.81,130.06 203.75,130.5 203.25,130.5 202.68,130.39 202.19,130.06 200.41,128.29 200.09,128.29 198.31,130.06 197.82,130.39 197.25,130.5 196.75,130.5 195.69,130.06 195.25,129 81.25,129 80.81,130.06 79.75,130.5 79.25,130.5 78.68,130.39 78.19,130.06 76.41,128.29 76.09,128.29 74.31,130.06 73.82,130.39 73.25,130.5 72.75,130.5 71.69,130.06 71.25,129 66,129 65.31,128.94 64.63,128.76 64,128.46 63.43,128.06 62.94,127.57 62.54,127 62.24,126.37 62.06,125.69 62,125 62,77 17.25,77 16.81,78.06 15.75,78.5 15.25,78.5 14.68,78.39 14.19,78.06 12.41,76.29 12.09,76.29 10.31,78.06 10.31,78.06 9.82,78.39 9.25,78.5 8.75,78.5 7.69,78.06 7.25,77 1,77 1,134 317.5,134 317.5,129 311.25,129 310.81,130.06 309.75,130.5 309.25,130.5 308.68,130.39 308.19,130.06 306.41,128.29 306.09,128.29 304.31,130.06 303.82,130.39 303.25,130.5 ; 4 cut-outs
PFC_OUT on TOP: 98.43,121.78 98.43,126.03 100.97,126.03 100.97,121.78
PFC_OUT on TOP: 133.88,54.36 133.88,58.26 136.48,58.26 136.48,54.36
PFC_OUT on BOTTOM: 97.5,114.25 97.46,114.26 97.45,114.3 97.45,120.17 97.87,121.59 98,123.05 98,123.05 98,125.55 98,125.57 98.01,125.59 98.4,125.98 98.43,126.02 98.47,126.03 100.92,126.03 100.95,126.03 103.91,126.03 103.93,126.02 103.94,126.01 104.4,125.56 104.4,121.86 104.41,121.54 104.45,121.22 104.45,114.3 104.44,114.26 104.4,114.25
PFC_OUT on BOTTOM: 155.25,26.15 155.22,26.16 155.21,26.2 155.21,33.1 155.22,33.14 155.25,33.15 157.1,33.15 157.35,33.22 157.46,33.3 158.1,33.94 158.23,34.17 158.25,34.3 158.25,49.68 158.25,49.7 158.26,49.71 161.27,52.72 161.3,52.73 162.12,52.73 162.94,52.89 163.63,53.35 164.26,53.98 164.72,54.67 164.88,55.49 164.88,58 164.88,58.02 164.89,58.03 165.08,58.22 165.08,58.26 167.68,58.26 167.68,58.22 167.87,58.03 167.88,58.02 167.88,58 167.88,50.55 167.88,50.53 167.87,50.52 163.41,46.06 163.27,45.82 163.25,45.68 163.25,32.75 163.28,32.65 163.35,32.58 163.45,32.55 163.75,32.55 163.85,32.58 163.92,32.65 163.95,32.75 163.95,34.3 163.96,34.34 164,34.35 166.03,34.35 166.05,34.35 166.06,34.34 172.64,27.76 172.65,27.75 172.65,27.73 172.65,26.2 172.64,26.16 172.6,26.15
PFC_OUT on BOTTOM: 128.85,26.15 128.81,26.16 128.8,26.2 128.8,30.18 128.8,30.2 128.81,30.21 133.55,34.95 133.68,35.18 133.7,35.31 133.7,53.36 133.68,53.42 133.68,58 133.68,58.02 133.69,58.03 133.88,58.22 133.88,58.26 136.48,58.26 136.48,58.22 137.49,57.21 137.5,57.18 137.5,56.25 137.5,56.25 137.8,54.45 138.69,52.86 138.7,52.82 138.7,26.2 138.69,26.16 138.65,26.15
PFC_OUT on BOTTOM: 174.62,14.45 174.6,14.45 174.59,14.46 173.86,15.19 173.85,15.2 173.85,15.22 173.85,16.55 173.86,16.59 173.9,16.6 175.8,16.6 175.84,16.59 175.85,16.55 175.85,15.02 175.85,15 175.84,14.99 175.31,14.46 175.3,14.45 175.28,14.45
PN on TOP: 141.21,53.5 141.21,58.9 144.39,58.9 144.39,53.5
PN on TOP: 143.95,97.3 143.93,97.3 143.91,97.31 143.65,97.58 143.64,97.6 143.6,97.76 143.6,102.98 143.6,103 143.61,103.01 143.89,103.29 143.9,103.3 143.92,103.3 147.6,103.3 147.86,103.56 147.9,103.59 147.96,103.6 148.1,103.6 148.21,103.56 148.25,103.45 148.25,102.77 148.25,102.75 148.24,102.74 148.03,102.53 148.03,101.9 148.01,101.86 147.97,101.85 147.03,101.85 146.32,101.15 146.32,97.45 146.28,97.34 146.18,97.3
PN on TOP: 123.43,121.78 123.43,126.03 125.97,126.03 125.97,121.78
PN on TOP: 164.31,78.8 164.31,84.2 167.49,84.2 167.49,78.8
PN on TOP: 170.92,60.55 170.9,60.55 170.89,60.56 170.01,61.44 170,61.45 170,61.47 170,62.7 170.01,62.73 170.05,62.74 170.9,62.74 170.97,62.77 171,62.84 171,63.15 171.04,63.26 171.15,63.3 171.54,63.3 171.6,63.29 171.64,63.26 171.75,63.15 172.2,63.15 172.35,63.11 172.46,63 172.5,62.85 172.5,61.85 172.54,61.7 172.65,61.59 172.8,61.55 176.3,61.55 176.45,61.51 176.56,61.4 176.6,61.25 176.6,60.85 176.51,60.64 176.3,60.55
PN on TOP, BOTTOM: 170.71,121.1 170.71,126.5 173.89,126.5 173.89,121.1
PN on BOTTOM: 123.47,121.78 123.42,121.8 123.4,121.86 123.4,125.95 123.42,126.01 123.47,126.03 125.92,126.03 125.98,126.01 126,125.95 126,121.86 125.98,121.8 125.92,121.78
PN on BOTTOM: 203.97,24.4 203.94,24.41 203.93,24.45 203.93,25.64 203.9,25.74 203.87,25.78 202.71,26.94 202.62,26.99 202.57,27 201.95,27 201.91,27.01 201.9,27.05 201.9,29.15 201.91,29.19 201.95,29.2 202.53,29.2 202.55,29.2 202.56,29.19 205.49,26.26 205.5,26.25 205.5,26.23 205.5,24.45 205.49,24.41 205.45,24.4
PN on BOTTOM: 110.01,53.5 110.01,58.9 113.19,58.9 113.19,53.5
PN on CONDUCTIVE2: outline of 331 points within 82.25,0.5 235.4,126.5 ; 100 cut-outs
PN on CONDUCTIVE5: outline of 327 points within 82.25,0.5 235.4,126.5 ; 100 cut-outs
SIG1 on BOTTOM: 40.42,13 40.4,13 40.39,13.01 37.01,16.39 37,16.4 37,16.42 37,17.48 37,17.5 37.01,17.51 39,19.5 39,23.35 39.01,23.39 39.05,23.4 43.95,23.4 43.99,23.39 44,23.35 44,20.8 44.8,20 46.3,20 47.2,20.9 47.2,31.78 47.2,31.8 47.21,31.81 49.04,33.64 49.05,33.65 49.07,33.65 50.33,33.65 50.35,33.65 50.36,33.64 55.39,28.61 55.4,28.6 55.4,28.58 55.4,28.22 55.4,28.2 55.39,28.19 54.2,27 54.2,17.92 54.2,17.9 54.19,17.89 49.31,13.01 49.3,13 49.28,13
SIG1 on CONDUCTIVE4: 47.25,27.6 47.21,27.61 47.2,27.65 47.2,31.78 47.2,31.8 47.21,31.81 49.04,33.64 49.05,33.65 49.07,33.65 50.33,33.65 50.35,33.65 50.36,33.64 52.19,31.81 52.2,31.8 52.2,31.78 52.2,27.65 52.19,27.61 52.15,27.6
SIG1 on CONDUCTIVE5: 47.25,27.55 47.21,27.56 47.2,27.6 47.2,31.78 47.2,31.8 47.21,31.81 49.04,33.64 49.05,33.65 49.07,33.65 50.33,33.65 50.35,33.65 50.36,33.64 52.19,31.81 52.2,31.8 52.2,31.78 52.2,27.6 52.19,27.56 52.15,27.55
SIG2 on TOP: 32.32,2.8 32.3,2.8 32.29,2.81 29.46,5.64 29.45,5.65 29.45,5.67 29.45,7.75 20.62,16.58 20.61,16.6 20.6,16.62 20.6,25.26 20.59,25.28 20.59,25.3 20.59,28.65 20.6,28.69 20.64,28.7 34.73,28.7 34.75,28.7 34.76,28.69 36.43,27.02 36.45,27 36.45,26.98 36.45,21.81 36.44,21.75 36.41,21.71 34.45,19.75 34.45,13.95 38.5,9.9 51.08,9.9 51.1,9.9 51.11,9.89 52.24,8.76 52.25,8.75 52.25,8.73 52.25,4.57 52.25,4.55 52.24,4.54 50.54,2.84 50.5,2.81 50.44,2.8
SIG2 on BOTTOM: 37.55,1.5 37.44,1.54 37.4,1.65 37.4,2.8 32.32,2.8 32.3,2.8 32.29,2.81 29.46,5.64 29.45,5.65 29.45,5.67 29.45,7.75 20.62,16.58 20.61,16.6 20.6,16.62 20.6,25.26 20.59,25.28 20.59,25.3 20.59,28.65 20.6,28.69 20.64,28.7 34.73,28.7 34.75,28.7 34.76,28.69 36.44,27.01 36.45,27 36.45,26.98 36.45,21.81 36.44,21.75 36.41,21.71 34.45,19.75 34.45,13.95 38.5,9.9 52.2,9.9 52.24,9.89 52.25,9.85 52.25,4.61 52.21,4.51 50.54,2.84 50.44,2.8 42.15,2.8 42.15,1.65 42.11,1.54 42,1.5
SIG6 on TOP (solid shape): 117.45,123.3 117.74,123.94 118.38,123.66 119.01,122.03 118.9,121.5 118.37,121.39 116.74,122.02 116.51,122.2 116.42,122.48 116.64,122.89 117.1,122.95 117.2,122.91 117.49,123.19
SIG6 on TOP: 116.56,94 116.5,94.01 116.46,94.04 114.69,95.81 114.65,95.91 114.65,96.5 114.33,98.06 113.42,99.37 113.4,99.4 113.4,106.39 113.33,106.64 113.25,106.75 110.65,109.35 110.42,109.48 110.29,109.5 79.87,109.5 79.85,109.5 79.84,109.51 76,113.35 75.77,113.48 75.64,113.5 74.69,113.5 74.44,113.43 74.34,113.35 74,113.01 73.98,113 73.96,113 71.6,113 71.56,113.01 71.55,113.05 71.55,116.45 71.56,116.49 71.6,116.5 111.23,116.5 111.25,116.5 111.26,116.49 119.19,108.56 119.2,108.55 119.2,108.53 119.2,99 120.25,99 120.36,98.96 120.4,98.85 120.4,95.46 120.39,95.4 120.36,95.36 119.04,94.04 119,94.01 118.94,94
SIG6 on TOP: 115.93,121.78 115.93,126.03 118.47,126.03 118.47,121.78
SIG6 on TOP: 108.2,7.25 108.16,7.26 108.15,7.3 108.15,17.55 108.16,17.59 108.2,17.6 115.1,17.6 115.14,17.59 115.15,17.55 115.15,10.87 115.15,10.85 115.14,10.84 111.56,7.26 111.55,7.25 111.53,7.25
SIG6 on BOTTOM: 116.91,94.58 116.72,94.61 116.55,94.72 115.55,95.73 115.44,95.89 115.4,96.08 115.4,96.8 115.39,96.83 114.6,99.28 112.73,101.05 112.71,101.06 112.7,101.09 112.7,119.1 112.71,119.12 113.79,120.32 114.17,121.86 114.17,125.48 114.17,125.5 114.18,125.51 114.66,125.99 114.67,126 114.69,126 115.92,126 115.94,126.02 115.97,126.03 118.42,126.03 118.46,126.02 118.48,126 119.18,126 119.2,126 119.21,125.99 119.69,125.51 119.7,125.5 119.7,125.48 119.7,112.92 120.22,112.12 120.4,111.19 120.4,96.56 120.36,96.37 120.25,96.2 118.77,94.72 118.61,94.61 118.42,94.58
SIG8 on TOP (solid shape): 109.95,123.3 110.24,123.94 110.88,123.66 111.51,122.03 111.4,121.5 110.87,121.39 109.24,122.02 109.01,122.2 108.92,122.48 109.14,122.89 109.6,122.95 109.7,122.91 109.99,123.19
SIG8 on TOP: 108.43,121.78 108.43,126.03 110.97,126.03 110.97,121.78
SIG8 on BOTTOM: 108.47,121.78 108.42,121.8 108.4,121.86 108.4,125.95 108.42,126.01 108.47,126.03 110.92,126.03 110.98,126.01 111,125.95 111,121.86 110.98,121.8 110.92,121.78
SIG8 on BOTTOM: 70.85,66.35 70.81,66.36 70.8,66.4 70.8,78.51 70.8,78.53 70.81,78.54 78.15,85.88 78.28,86.11 78.3,86.24 78.3,93.21 78.23,93.46 78.15,93.57 75.39,96.33 75.32,96.43 75.3,96.54 75.3,98.38 75.3,98.4 75.31,98.41 76.04,99.14 76.05,99.15 76.07,99.15 78.85,99.15 78.89,99.15 78.93,99.14 85.25,99.14 85.29,99.13 85.3,99.09 85.3,83.17 85.3,83.15 85.29,83.14 77.95,75.8 77.82,75.57 77.8,75.44 77.8,69.29 77.8,69.27 77.79,69.26 74.89,66.36 74.88,66.35 74.86,66.35
SIG8 on CONDUCTIVE4, CONDUCTIVE5: 77.02,95.25 76.95,95.26 76.81,95.34 76.54,95.61 76.49,95.67 76.45,95.82 76.45,98.15 76.49,98.3 76.6,98.41 76.75,98.45 78.85,98.45 79,98.41 79.11,98.3 79.15,98.15 79.15,95.55 79.11,95.4 79,95.29 78.85,95.25
SIG11 on BOTTOM: 133.91,94.79 133.86,94.9 133.91,95.01 136.96,98.06 137,98.09 137.06,98.1 139.44,98.1 139.5,98.09 139.54,98.06 140.46,97.14 140.49,97.1 140.5,97.04 140.5,95.24 140.3,94.76 140.15,94.25 137.41,91.51 137.3,91.46 137.19,91.51
SIG11 on BOTTOM: 158.12,54.81 158.1,54.81 158.09,54.82 157.79,55.12 157.78,55.13 157.78,55.15 157.78,56.18 156.58,59.1 153.65,60.3 152.65,60.3 152.63,60.3 152.62,60.31 151.66,61.27 151.61,61.33 151.56,61.38 144.85,68.08 144.4,68.44 143.88,68.69 143.47,68.8 143.05,68.83 141.15,68.83 141.04,68.83 141.02,68.83 141.01,68.84 139.29,70.56 139.26,70.59 139.22,70.68 139.2,70.77 139.2,73.73 139.24,73.88 139.35,73.99 139.5,74.03 143.88,74.03 143.9,74.03 143.91,74.02 151.56,66.3 152.07,65.86 152.66,65.52 153.3,65.29 153.96,65.17 154.32,65.15 155.48,65.15 155.5,65.15 155.51,65.14 162.79,57.86 162.8,57.85 162.8,57.83 162.8,55.49 162.8,55.47 162.79,55.45 162.16,54.82 162.14,54.81 162.12,54.81
SIG12 on TOP: 128.8,54.36 128.8,58.26 131.4,58.26 131.4,54.36
SIG12 on BOTTOM: 128.8,54.36 128.8,55.88 123.43,61.25 123.42,61.26 123.42,61.28 123.41,61.3 123.41,61.32 123.41,64.53 123.2,65.55 122.63,66.41 121.19,67.85 120.33,68.42 119.31,68.62 118.61,68.62 118.55,68.64 118.51,68.67 116.79,70.39 116.72,70.48 116.7,70.6 116.7,75.1 116.79,75.31 117,75.4 121.2,75.4 121.55,75.25 121.7,74.9 121.7,72.27 121.72,72.16 121.79,72.06 127.68,66.17 127.69,66.16 127.69,66.14 127.69,63.16 131.39,59.47 131.4,59.45 131.4,59.43 131.4,54.36
SIG18 on TOP: 146.66,53.5 146.66,58.9 149.84,58.9 149.84,53.5
SIG18 on BOTTOM: 146.66,53.5 146.66,56.22 145.48,58.98 142.66,60.06 141.77,60.06 141.75,60.06 141.74,60.07 140.41,61.4 140.4,61.41 140.4,61.43 140.4,65.58 140.41,65.64 140.44,65.69 141.04,66.29 141.15,66.33 143.05,66.33 143.07,66.33 143.08,66.32 149.79,59.61 149.84,59.5 149.84,58.9 149.84,58.9 149.84,53.5
SIG22 on BOTTOM: 115.84,54.8 115.73,54.84 115.69,54.95 115.69,61.8 115.7,61.85 115.73,61.9 115.9,62.07 115.9,65.58 115.9,65.6 115.91,65.61 116.41,66.11 116.43,66.12 116.45,66.12 119.31,66.12 119.42,66.08 120.86,64.64 120.91,64.53 120.91,60.81 120.86,60.71 120.31,60.16 120.29,60.14 119.6,59.58 119.06,58.9 118.58,57.85 118.41,56.7 118.41,54.95 118.37,54.84 118.26,54.8
SIG82 on TOP, BOTTOM: 159.81,121.1 159.81,126.5 162.99,126.5 162.99,121.1
SIG91 on TOP: 171.27,63.75 171.24,63.76 171.22,63.77 169.68,63.77 169.64,63.79 169.62,63.83 169.62,64.45 169.64,64.49 169.68,64.5 171.45,64.5 171.69,64.74 171.7,64.75 171.72,64.75 176.78,64.75 176.8,64.75 176.81,64.74 177,64.55 178.05,64.55 178.09,64.54 178.1,64.5 178.1,63.9 178.09,63.86 178.05,63.85 177,63.85 176.91,63.76 176.9,63.75 176.88,63.75
SIG94 on TOP (solid shape): 153.99,64.46 153.94,64.67 154.15,64.71 155.04,64.13 155.11,64 155.04,63.87 154.15,63.29 153.94,63.33 153.99,63.54 154.14,63.64 154.14,64.36
SIG115 on BOTTOM: 252.32,60.85 252.3,60.85 252.29,60.86 249.03,64.12 248.86,64.23 248.67,64.27 245.85,64.27 245.74,64.29 245.64,64.36 243.4,66.6 243.32,66.71 243.25,66.96 243.25,78.69 243.27,78.82 243.4,79.05 245.24,80.89 245.25,80.9 245.27,80.9 249.03,80.9 249.05,80.9 249.06,80.89 249.8,80.15 249.91,79.98 249.95,79.79 249.95,70.53 249.99,70.34 250.1,70.17 251.2,69.07 251.36,68.96 251.55,68.92 253.78,68.92 253.81,68.91 253.82,68.88 253.82,64.42 253.82,64.41 253.82,60.9 253.81,60.86 253.77,60.85
SIG135 on TOP: 237.02,108.9 236.99,108.91 235.31,110.59 235.3,110.62 235.3,114.61 235.3,114.63 235.31,114.68 235.3,114.75 235.3,124.53 235.3,124.55 235.31,124.56 236.96,126.21 237.01,126.24 237.06,126.25 254.78,126.25 254.81,126.24 255.31,125.74 255.32,125.72 255.32,125.7 255.32,120.6 255.31,120.56 255.06,120.31 255.03,120.3 251.96,120.3 251.71,120.23 251.6,120.15 251.31,119.86 251.27,119.79 251.25,119.72 251.25,118.55 251.24,118.51 251.2,118.5 250.78,118.5 250.76,118.5 250.74,118.51 249.51,119.75 249.5,119.75 247.15,120.81 244.8,119.75 244.79,119.75 242.83,117.68 242.75,117.29 242.75,116.44 242.75,116.39 242.75,110.62 242.75,110.6 242.74,110.59 241.06,108.91 241.03,108.9
SIG135 on BOTTOM: 237.02,108.9 236.99,108.91 235.31,110.59 235.3,110.62 235.3,114.61 235.3,114.63 235.31,114.68 235.3,114.75 235.3,124.53 235.3,124.55 235.31,124.56 236.96,126.21 237.01,126.24 237.06,126.25 254.78,126.25 254.81,126.24 255.31,125.74 255.32,125.7 255.32,117.55 255.31,117.51 255.28,117.5 251.77,117.5 251.75,117.5 251.74,117.51 251.02,118.23 250.99,118.26 250.86,118.39 250.44,118.81 250.39,118.87 249.51,119.75 247.15,120.81 244.8,119.75 244.48,119.44 243.04,118 242.83,117.68 242.75,117.29 242.75,110.62 242.75,110.6 242.74,110.59 241.06,108.91 241.03,108.9
SIG199 on TOP: 72.95,30.75 72.84,30.79 72.8,30.9 72.8,35.34 72.81,35.4 72.84,35.44 74.21,36.81 74.25,36.84 74.31,36.85 76.04,36.85 76.1,36.84 76.14,36.81 77.46,35.49 77.49,35.45 77.5,35.39 77.5,30.9 77.46,30.79 77.35,30.75
SIG199 on BOTTOM: 72.95,30.75 72.84,30.79 72.8,30.9 72.8,35.34 72.81,35.4 72.84,35.44 74.21,36.81 74.25,36.84 74.31,36.85 77.44,36.85 77.5,36.84 77.54,36.81 78.86,35.49 78.89,35.45 78.9,35.39 78.9,30.9 78.86,30.79 78.75,30.75
SIG200 on TOP, BOTTOM: 85.16,6.5 85.1,6.51 85.06,6.54 84.92,6.68 84.9,6.71 84.88,6.73 84.71,7.14 84.52,7.53 84.5,7.56 84.5,7.6 84.5,11.5 84.54,11.61 84.65,11.65 89.35,11.65 89.46,11.61 89.5,11.5 89.5,6.96 89.46,6.86 89.31,6.71 89.29,6.69 89.26,6.68 89.08,6.6 88.9,6.52 88.87,6.5 88.83,6.5
SIG200 on TOP, BOTTOM: 74.8,15.75 74.76,15.76 74.75,15.8 74.75,21.7 74.76,21.74 74.8,21.75 81.05,21.75 81.09,21.74 81.1,21.7 81.1,15.8 81.09,15.76 81.05,15.75
SIG200 on TOP, BOTTOM: 67.06,6.5 67,6.51 66.96,6.54 66.44,7.06 66.4,7.16 66.4,11.5 66.44,11.61 66.55,11.65 71.25,11.65 71.36,11.61 71.4,11.5 71.4,7.78 71.4,7.74 71.38,7.71 71.13,7.23 70.92,6.73 70.9,6.71 70.88,6.68 70.74,6.54 70.7,6.51 70.64,6.5
SIG205 on TOP: 175.21,78.8 175.21,84.2 178.39,84.2 178.39,78.8
SIG206 on TOP (solid shape): 158.13,83.06 158.19,83.18 158.33,83.2 159.8,82.72 159.88,82.66 159.91,82.57 159.84,82.45 159.71,82.43 159.41,82.53 158.42,81.82 158.42,81.51 158.27,81.36 158.12,81.51
SIG249 on TOP (solid shape): 173.18,117.76 173.13,117.97 173.34,118.01 174.23,117.43 174.3,117.3 174.23,117.17 173.34,116.59 173.13,116.63 173.18,116.84 173.33,116.94 173.33,117.66
SIG249 on TOP: 165.26,121.1 165.26,126.5 168.44,126.5 168.44,121.1
SIG249 on TOP, BOTTOM: 152.81,121.1 152.81,126.5 155.99,126.5 155.99,121.1
SIG249 on CONDUCTIVE3: 163.71,96.5 163.61,96.54 161.54,98.61 161.5,98.71 161.5,109.67 161.47,110.02 161.38,110.36 161.23,110.67 161.03,110.96 160.91,111.09 158.69,113.31 158.04,113.75 157.27,113.9 154.99,113.9 154.95,113.91 151.58,117.27 151.56,117.3 151.55,117.34 151.55,120.63 151.55,120.65 151.57,120.67 152.29,121.44 152.78,122.38 152.8,122.4 152.8,122.43 152.98,123.12 153.04,123.8 153.04,125.25 153.08,125.36 153.19,125.4 156.56,125.4 156.67,125.36 156.71,125.25 156.71,123.8 157.21,121.85 158.57,120.37 163.75,120.37 164.4,121.02 165.21,122.31 165.49,123.8 165.49,125.3 165.53,125.41 165.64,125.45 168.06,125.45 168.17,125.41 168.21,125.3 168.21,123.8 168.24,123.3 168.45,122.44 168.59,122.09 168.6,122.06 168.6,122.03 168.62,122.02 168.63,122 170.24,120.27 172.55,119.72 172.55,119.72 174.21,119.72 174.23,119.72 174.24,119.71 174.46,119.49 174.53,119.39 174.55,119.28 174.55,105.15 174.54,105.12 172.41,103.57 171.6,101.1 171.6,97.57 171.6,97.55 171.59,97.54 170.56,96.51 170.55,96.5 170.53,96.5
SIGN267 on TOP: 120.91,53.5 120.91,58.9 124.09,58.9 124.09,53.5
SIGN355 on TOP: 191.07,64.25 191.05,64.25 191.04,64.26 187.76,67.54 187.75,67.55 187.75,67.57 187.75,74.53 187.75,74.55 187.76,74.56 188.14,74.94 188.15,74.95 188.17,74.95 190.28,74.95 190.3,74.95 190.31,74.94 191.6,73.65 191.6,68.33 191.65,67.8 191.81,67.3 191.88,67.15 191.91,67.07 192.31,65.89 192.45,64.64 192.45,64.3 192.44,64.26 192.4,64.25
SIGN355 on BOTTOM: outline of 108 points within 146.43,64.4 192.45,126.5
